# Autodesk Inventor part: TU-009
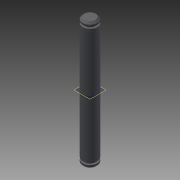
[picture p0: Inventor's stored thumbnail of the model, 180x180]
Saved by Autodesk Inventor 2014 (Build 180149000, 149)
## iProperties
Shininess: 64.0
Angle Display Precision: 2
Document Length Units: 11269
Document Angle Units: 11279
Document Time Units: 11290
Document Mass Units: 11286
Document Length Units Precision: 3
Document Angle Units Precision: 2
Compacted: True
Created: 2002-07
Part Number: TU-009
Document SubType Name: Modeling
Designer: PN
Description: Long Pin
Density: 8.08 g/cm^3
Mass: 27.8886 g
Surface Area: 19.0317 cm^2
Volume: 3.45156 cm^3
Material: Stainless Steel
Appearance: 128,128,128
Density: 0.0
Volumn: 0.0
Area: 0.0
PropertySet Name: Model Information
Control State: 0
Master: False
Checked Out: False
LENGTH: 1.000 in
Author: PN
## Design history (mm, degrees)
sketch "Sketch1"
  geometry: L1 (4, 67)-(4, 3); L2 (3, 67)-(4, 67); L3 (3, 68)-(3, 67); L4 (4, 68)-(3, 68); L5 (4, 69)-(4, 68); L6 (0, 70)-(3, 70); L7 (3, 70)-(4, 69); L8 (4, 3)-(3, 3); L9 (3, 3)-(3, 2); L10 (3, 2)-(4, 2); L11 (4, 2)-(4, 1); L12 (4, 1)-(3, 0); L13 (0, 70)-(0, 0); L14 (0, 0)-(3, 0); 1 further point
  constraints: 28 end point, 5 perpendicular, 3 collinear, 2 equal length, 1 coincident, 1 horizontal, 1 parallel
  dimensions: "d4" = 65 distance between parallel lines of L4 L8; "d5" = 1 distance between parallel lines of L4 L2; "d6" = 66 distance between parallel lines of L4 L10; "d7" = 2 distance between parallel lines of L4 L6; "d19" = 8 diameter of L11 L13; "d20" = 45 deg angle of L14 L12; "d23" = 1 distance from line of L12.end L11; "d24" = 1 distance between parallel lines of L3 L1
revolve "Revolution1" sketch "Sketch1" stored, may be unused: angle "d18" = 90 deg
workplane "Work Plane1"
body "Solid1"
other parameters: "LENGTH" = 25.4 [user parameter]
